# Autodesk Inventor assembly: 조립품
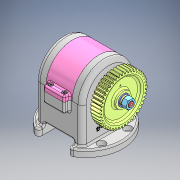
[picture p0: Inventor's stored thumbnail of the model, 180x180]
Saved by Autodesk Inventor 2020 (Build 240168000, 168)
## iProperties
Created: 2025-05
Part Number: 조립품
Document SubType Name: Assembly
Designer: 1강의실14
Author: 1강의실14
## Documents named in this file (21)
- C:\Users\1강의실14\Desktop\650503V1003\답안조립품.iam
- C:\Users\1강의실14\Desktop\650503V1003\본체.ipt
- C:\Users\1강의실14\Desktop\650503V1003\링크.ipt
- C:\Users\1강의실14\Desktop\650503V1003\부시 커버.ipt
- C:\Users\1강의실14\Desktop\650503V1003\스퍼 기어.ipt
- C:\Users\1강의실14\Desktop\650503V1003\스프링 와셔 M10.ipt
- C:\Users\1강의실14\Desktop\650503V1003\앞커버.ipt
- C:\Users\1강의실14\Desktop\650503V1003\오일레스 부시 20 15.ipt
- C:\Users\1강의실14\Desktop\650503V1003\오일실 20 32 5.ipt
- C:\Users\1강의실14\Desktop\650503V1003\윗커버.ipt
- C:\Users\1강의실14\Desktop\650503V1003\육각 너트 M10x1.ipt
- C:\Users\1강의실14\Desktop\650503V1003\육각 소켓 머리 볼트 M4x10.ipt
- C:\Users\1강의실14\Desktop\650503V1003\칼라.ipt
- C:\Users\1강의실14\Desktop\650503V1003\펀치.ipt
- C:\Users\1강의실14\Desktop\650503V1003\편심축.ipt
- C:\Users\1강의실14\Desktop\650503V1003\평와셔 M10.ipt
- C:\Users\1강의실14\Desktop\650503V1003\평행키 5x5x12.ipt
- C:\Users\1강의실14\Desktop\650503V1003\핀.ipt
- C:\Users\1강의실14\Desktop\650503V1003\E형 멈춤링 10-8.ipt
- C:\Users\1강의실14\Desktop\650503V1003\깊은 홈 볼 베어링 6904.ipt
- C:\Users\1강의실14\Desktop\650503V1003\뒷커버.ipt
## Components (2 placed, 2 different names)
1. 핀:1 — 각도:9, 각도:10
2. E형 멈춤링 10-8:1 — 각도:9
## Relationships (2: Angle 2)
- 각도:9 [Angle]: 핀:1 ↔ E형 멈춤링 10-8:1
- 각도:10 [Angle]: 핀:1
